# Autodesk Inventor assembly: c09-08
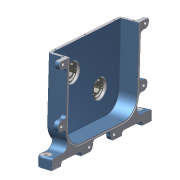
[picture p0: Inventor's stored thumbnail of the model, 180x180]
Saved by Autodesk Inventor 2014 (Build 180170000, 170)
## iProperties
Created: 2011-01
Part Number: c09-08
Document SubType Name: Assembly
Designer: Thom Tremblay
Author: Thom Tremblay
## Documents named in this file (3)
- C:\Inventor 2014 Essentials\Assemblies\Chapter 09\c09-08.iam
- C:\Inventor 2014 Essentials\Parts\Chapter 09\c09-13.ipt
- C:\Inventor 2014 Essentials\Assemblies\Chapter 09\Design Accelerators\Bearing c09-02.iam
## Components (3 placed, 2 different names)
1. c09-13:1 — Insert:1, Insert:2
2. Bearing:1 [sub-assembly] — Insert:1
3. Bearing:2 [sub-assembly] — Insert:2
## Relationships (2: Insert 2)
- Insert:1: c09-13:1 ↔ Bearing:1
- Insert:2: c09-13:1 ↔ Bearing:2
